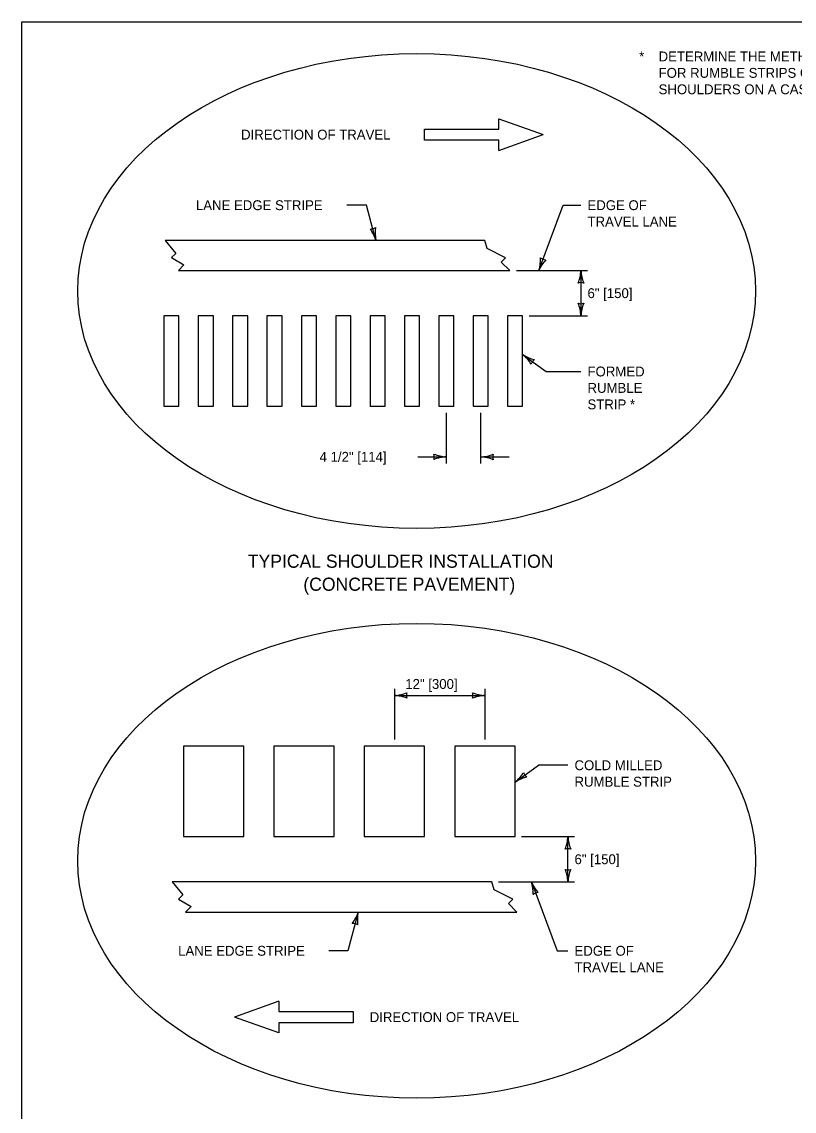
# Model space of a CAD drawing. Extents: x 49991.4 to 50021, y 49987.6 to 50011.4.
# Drawn here: x 49999.38 to 50004.09, y 49992.37 to 49999 of the extents above; entities that cross this region are included whole.
import ezdxf

# ---------------------------------------------------------------- set-up
doc = ezdxf.new("R2010")
doc.units = 0
for name, color, linetype in [('Level 1', 7, 'Continuous'), ('Level 2', 7, 'Continuous'), ('Level 3', 7, 'Continuous')]:
    doc.layers.add(name, color=color, linetype=linetype)

msp = doc.modelspace()

# ---------------------------------------------------------------- linework, layer by layer
at = {"layer": 'Level 1'}
for p, q in [((50002.2881, 49998.3467), (50002.2881, 49998.4089)), ((50002.2881, 49998.4089), (50002.5569, 49998.3128)), ((50001.834, 49998.2788), (50001.834, 49998.3467)), ((50001.834, 49998.3467), (50002.2881, 49998.3467)), ((50002.2881, 49998.2166), (50002.5569, 49998.3128)), ((50002.2881, 49998.2788), (50001.834, 49998.2788)), ((50002.2881, 49998.2166), (50002.2881, 49998.2788)), ((50002.2015, 49997.6696), (50000.2553, 49997.6696)), ((50000.2553, 49997.6696), (50000.3207, 49997.5907)), ((50002.2156, 49997.6209), (50002.2015, 49997.6696)), ((50002.3282, 49997.5636), (50002.2156, 49997.6209)), ((50000.3207, 49997.5907), (50000.2946, 49997.5645)), ((50000.2946, 49997.5645), (50000.3704, 49997.5203)), ((50002.302, 49997.5376), (50002.3282, 49997.5636)), ((50000.3704, 49997.5203), (50000.3365, 49997.4861)), ((50002.3539, 49997.4861), (50002.302, 49997.5376)), ((50000.3365, 49997.4861), (50002.3539, 49997.4861)), ((50002.2452, 49993.7677), (50000.299, 49993.7677)), ((50000.299, 49993.7677), (50000.3644, 49993.6888)), ((50002.2593, 49993.719), (50002.2452, 49993.7677)), ((50002.3719, 49993.6617), (50002.2593, 49993.719)), ((50000.3644, 49993.6888), (50000.3383, 49993.6626)), ((50000.3383, 49993.6626), (50000.4141, 49993.6184)), ((50002.3457, 49993.6357), (50002.3719, 49993.6617)), ((50000.4141, 49993.6184), (50000.3802, 49993.5842)), ((50000.3802, 49993.5842), (50002.3976, 49993.5842)), ((50002.3976, 49993.5842), (50002.3457, 49993.6357)), ((50000.9474, 49993.0411), (50000.6786, 49992.9449)), ((50000.9474, 49993.0411), (50000.9474, 49992.9789)), ((50000.9474, 49992.8488), (50000.6786, 49992.9449)), ((50000.9474, 49992.9789), (50001.4015, 49992.9789)), ((50001.4015, 49992.9789), (50001.4015, 49992.911)), ((50001.4015, 49992.911), (50000.9474, 49992.911)), ((50000.9474, 49992.911), (50000.9474, 49992.8488))]:
    msp.add_line(p, q, dxfattribs=at)
for points in [[(49999.3835, 49998.9992), (50016.7501, 49998.9992), (50016.7501, 49987.7988), (49999.3835, 49987.7988)], [(50000.3403, 49997.2109), (50000.2485, 49997.2109), (50000.2485, 49996.6604), (50000.3403, 49996.6604)], [(50000.5495, 49997.2109), (50000.4577, 49997.2109), (50000.4577, 49996.6604), (50000.5495, 49996.6604)], [(50000.7587, 49997.2109), (50000.6669, 49997.2109), (50000.6669, 49996.6604), (50000.7587, 49996.6604)], [(50000.9679, 49997.2109), (50000.8761, 49997.2109), (50000.8761, 49996.6604), (50000.9679, 49996.6604)], [(50001.1771, 49997.2109), (50001.0853, 49997.2109), (50001.0853, 49996.6604), (50001.1771, 49996.6604)], [(50001.3863, 49997.2109), (50001.2945, 49997.2109), (50001.2945, 49996.6604), (50001.3863, 49996.6604)], [(50001.5955, 49997.2109), (50001.5037, 49997.2109), (50001.5037, 49996.6604), (50001.5955, 49996.6604)], [(50001.8047, 49997.2109), (50001.7129, 49997.2109), (50001.7129, 49996.6604), (50001.8047, 49996.6604)], [(50002.0139, 49997.2109), (50001.9221, 49997.2109), (50001.9221, 49996.6604), (50002.0139, 49996.6604)], [(50002.2231, 49997.2109), (50002.1313, 49997.2109), (50002.1313, 49996.6604), (50002.2231, 49996.6604)], [(50002.4323, 49997.2109), (50002.3405, 49997.2109), (50002.3405, 49996.6604), (50002.4323, 49996.6604)], [(50000.7345, 49994.5934), (50000.3675, 49994.5934), (50000.3675, 49994.0429), (50000.7345, 49994.0429)], [(50001.285, 49994.5934), (50000.918, 49994.5934), (50000.918, 49994.0429), (50001.285, 49994.0429)], [(50001.8355, 49994.5934), (50001.4685, 49994.5934), (50001.4685, 49994.0429), (50001.8355, 49994.0429)], [(50002.386, 49994.5934), (50002.019, 49994.5934), (50002.019, 49994.0429), (50002.386, 49994.0429)]]:
    msp.add_lwpolyline(points, close=True, dxfattribs=at)
for centre in [(50001.787, 49997.3618), (50001.787, 49993.8958)]:
    msp.add_ellipse(centre, major_axis=(-2.0626, 0), ratio=0.700037, dxfattribs=at)
at = {"layer": 'Level 3'}
for p, q in [((50001.4817, 49997.8836), (50001.3618, 49997.8836)), ((50001.5396, 49997.6696), (50001.4817, 49997.8836)), ((50002.5308, 49997.4861), (50002.6795, 49997.8836)), ((50002.6795, 49997.8836), (50002.7868, 49997.8836)), ((50002.3939, 49997.4861), (50002.8269, 49997.4861)), ((50002.7869, 49997.4861), (50002.7869, 49997.2109)), ((50002.4723, 49997.2109), (50002.8269, 49997.2109)), ((50002.4323, 49996.9754), (50002.576, 49996.8721)), ((50002.576, 49996.8721), (50002.7869, 49996.8721)), ((50001.968, 49996.3131), (50001.968, 49996.6204)), ((50002.1772, 49996.3125), (50002.1772, 49996.6204)), ((50001.7946, 49996.3531), (50001.968, 49996.3531)), ((50002.1772, 49996.3525), (50002.3506, 49996.3525)), ((50001.652, 49994.9413), (50001.652, 49994.6334)), ((50002.2025, 49994.9413), (50002.2025, 49994.6334)), ((50001.652, 49994.9013), (50002.2025, 49994.9013)), ((50002.386, 49994.3741), (50002.5292, 49994.477)), ((50002.7079, 49994.477), (50002.5292, 49994.477)), ((50002.426, 49994.0429), (50002.7479, 49994.0429)), ((50002.7079, 49993.7677), (50002.7079, 49994.0429)), ((50002.2852, 49993.7677), (50002.7479, 49993.7677)), ((50002.4852, 49993.7677), (50002.6421, 49993.3483)), ((50001.4313, 49993.5842), (50001.3675, 49993.3483)), ((50001.3675, 49993.3483), (50001.2534, 49993.3483)), ((50002.6421, 49993.3483), (50002.7079, 49993.3483))]:
    msp.add_line(p, q, dxfattribs=at)
for centre, radius, start, end in [((50001.5061, 49997.7934), 0.0548, 267.27503, 302.99739), ((50001.3276, 49997.6028), 0.2223, 17.49669, 37.68019), ((50001.7672, 49997.7193), 0.233, 173.05904, 192.30889), ((50002.3196, 49997.5554), 0.2223, 341.84877, 2.03228), ((50002.5757, 49997.6062), 0.0548, 231.62711, 267.34947), ((50002.7448, 49997.3938), 0.233, 137.41113, 156.66098), ((50002.5647, 49997.4953), 0.2223, 337.45601, 357.63952), ((50003.0196, 49997.4976), 0.233, 182.82731, 202.07716), ((50002.7869, 49997.3579), 0.0548, 72.13882, 107.86118), ((50002.7869, 49997.3391), 0.0548, 252.13882, 287.86118), ((50002.5541, 49997.1994), 0.233, 2.82731, 22.07716), ((50003.009, 49997.2017), 0.2223, 157.45601, 177.63952), ((50002.2952, 49996.8004), 0.2223, 31.74521, 51.92872), ((50002.5588, 49997.1711), 0.233, 237.11651, 256.36636), ((50002.5364, 49996.9006), 0.0548, 126.42802, 162.15038), ((50001.9772, 49996.5752), 0.2223, 247.45601, 267.63952), ((50001.8398, 49996.3531), 0.0548, 342.13882, 17.86118), ((50002.1657, 49996.5852), 0.233, 272.82731, 292.07716), ((50002.3054, 49996.3525), 0.0548, 162.13882, 197.86118), ((50001.9795, 49996.1204), 0.233, 92.82731, 112.07716), ((50002.168, 49996.1304), 0.2223, 67.45601, 87.63952), ((50001.6405, 49995.134), 0.233, 272.82731, 292.07716), ((50001.7802, 49994.9013), 0.0548, 162.13882, 197.86118), ((50002.2117, 49995.1234), 0.2223, 247.45601, 267.63952), ((50002.0743, 49994.9013), 0.0548, 342.13882, 17.86118), ((50001.6428, 49994.6792), 0.2223, 67.45601, 87.63952), ((50002.214, 49994.6686), 0.233, 92.82731, 112.07716), ((50002.2408, 49994.5563), 0.233, 308.53811, 327.78796), ((50002.5082, 49994.1884), 0.2223, 103.16681, 123.35032), ((50002.4901, 49994.4489), 0.0548, 197.84962, 233.57198), ((50002.4858, 49994.0521), 0.2223, 337.45601, 357.63952), ((50002.9406, 49994.0544), 0.233, 182.82731, 202.07716), ((50002.7079, 49993.9147), 0.0548, 72.13882, 107.86118), ((50002.7079, 49993.8959), 0.0548, 252.13882, 287.86118), ((50002.4752, 49993.7562), 0.233, 2.82731, 22.07716), ((50002.93, 49993.7585), 0.2223, 157.45601, 177.63952), ((50002.2739, 49993.6984), 0.2223, 357.96772, 18.15123), ((50002.6991, 49993.86), 0.233, 203.33902, 222.58887), ((50002.5301, 49993.6476), 0.0548, 92.65053, 128.37289), ((50001.2193, 49993.651), 0.2223, 322.31981, 342.50331), ((50001.659, 49993.5345), 0.233, 167.69111, 186.94096), ((50001.3978, 49993.4604), 0.0548, 57.00261, 92.72498)]:
    msp.add_arc(centre, radius, start, end, dxfattribs=at)

# ---------------------------------------------------------------- texts
at = {"layer": 'Level 2'}
for s, height, p in [('*', 0.06, (50003.1413, 49998.7585)), ('DETERMINE THE METHOD OF INSTALLATION', 0.06, (50003.2598, 49998.7585)), ('FOR RUMBLE STRIPS ON EXISTING CONCRETE', 0.06, (50003.2598, 49998.6585)), ('SHOULDERS ON A CASE-BY-CASE BASIS.', 0.06, (50003.2598, 49998.5585)), ('DIRECTION OF TRAVEL', 0.06, (50000.7184, 49998.2828)), ('LANE EDGE STRIPE', 0.06, (50000.4435, 49997.8536)), ('EDGE OF', 0.06, (50002.8269, 49997.8536)), ('TRAVEL LANE', 0.06, (50002.8269, 49997.7536)), ('6" [150]', 0.06, (50002.8269, 49997.3185)), ('4 1/2" [114]', 0.06, (50001.1962, 49996.3231)), ('TYPICAL SHOULDER INSTALLATION', 0.08, (50000.7592, 49995.6781)), ('(CONCRETE PAVEMENT)', 0.08, (50001.0974, 49995.5381)), ('12" [300]', 0.06, (50001.7178, 49994.9413)), ('COLD MILLED', 0.06, (50002.7479, 49994.447)), ('RUMBLE STRIP', 0.06, (50002.7479, 49994.347)), ('6" [150]', 0.06, (50002.7479, 49993.8753)), ('LANE EDGE STRIPE', 0.06, (50000.3351, 49993.3183)), ('EDGE OF ', 0.06, (50002.7479, 49993.3183)), ('TRAVEL LANE', 0.06, (50002.7479, 49993.2183)), ('DIRECTION OF TRAVEL', 0.06, (50001.5015, 49992.915))]:
    msp.add_text(s, height=height, dxfattribs=at).set_placement(p)
for s, p in [('FORMED', (50002.8269, 49996.8421)), ('RUMBLE', (50002.8269, 49996.7421)), ('STRIP *', (50002.8269, 49996.6421))]:
    msp.add_text(s, height=0.06, rotation=0.00005, dxfattribs=at).set_placement(p)

doc.saveas('drawing.dxf')
